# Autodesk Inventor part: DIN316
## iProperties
Shininess: 64.0
Length Units: 11269
Angle Units: 11279
Time Units: 11290
Mass Units: 11283
Length Display Precision: 3
Angle Display Precision: 2
Compacted: True
Created: 2003-04
Part Number: DIN316
Material: St.Galvanized
Document SubType Name: Modeling
Designer: Robbert Osinga
Description: Wingscrew M4x8
Density: 0.0
Volumn: 0.0
Area: 0.0
PropertySet Name: Model Information
Control State: 0
Master: False
Checked Out: False
Checked Out By: ?
Author: Robbert Osinga
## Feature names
1. Extrusion2
2. Extrusion4
3. Revolution2
4. Fillet8
5. Fillet9
6. Fillet10
7. Extrusion6
8. Chamfer2
